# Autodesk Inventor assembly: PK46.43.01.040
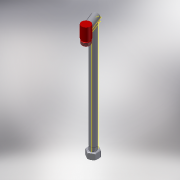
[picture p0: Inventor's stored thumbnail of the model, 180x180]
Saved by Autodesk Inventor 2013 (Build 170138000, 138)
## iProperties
Shininess: 64.0
Length Units: 11269
Angle Units: 11279
Time Units: 11290
Mass Units: 11283
Length Display Precision: 3
Angle Display Precision: 2
Compacted: True
Created: 2004-12
Part Number: PK46.43.01.040
Document SubType Name: Assembly
Designer: ELarisa
Manufacturer: Standard
Standards Organization: Custom
Density: 0.0
Volumn: 0.0
Area: 0.0
PropertySet Name: Model Information
Control State: 0
Master: False
Checked Out: False
Checked Out Date: 2008-10-09
Last Check In Date: 2008-10-09
Author: ELarisa
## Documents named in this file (6)
- C:\Product Design Suite 2013 Test Drive\Dynamic Simulation\Workspace\Assy, Chassis, Front\PK46.43.01.040.iam
- C:\Product Design Suite 2013 Test Drive\Dynamic Simulation\Workspace\Assy, Chassis, Front\PK46.43.01.017.ipt
- C:\Product Design Suite 2013 Test Drive\Dynamic Simulation\Workspace\Assy, Chassis, Front\PK46.43.01.012.ipt
- C:\Product Design Suite 2013 Test Drive\Dynamic Simulation\Workspace\Assy, Chassis, Front\027.08.00.004.ipt
- C:\Product Design Suite 2013 Test Drive\Dynamic Simulation\Workspace\Assy, Chassis, Front\027.07.03.005.ipt
- C:\Product Design Suite 2013 Test Drive\Dynamic Simulation\Workspace\Assy, Chassis, Front\027.04.04.012.ipt
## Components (5 placed, 5 different names)
1. PK46.43.01.017:1 — Вставка:6
2. 027.08.00.004:1 — Вставка:3, Угол:1
3. 027.07.03.005:1 — Вставка:3, Вставка:6
4. 027.04.04.012:1 — Вставка:5, Угол:1
5. PK46.43.01.012:1 — Вставка:5
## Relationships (4: Insert 3, Angle 1)
- Вставка:3 [Insert]: 027.08.00.004:1 ↔ 027.07.03.005:1
- Вставка:5 [Insert]: 027.04.04.012:1 ↔ PK46.43.01.012:1
- Угол:1 [Angle]: 027.08.00.004:1 ↔ 027.04.04.012:1
- Вставка:6 [Insert]: PK46.43.01.017:1 ↔ 027.07.03.005:1
